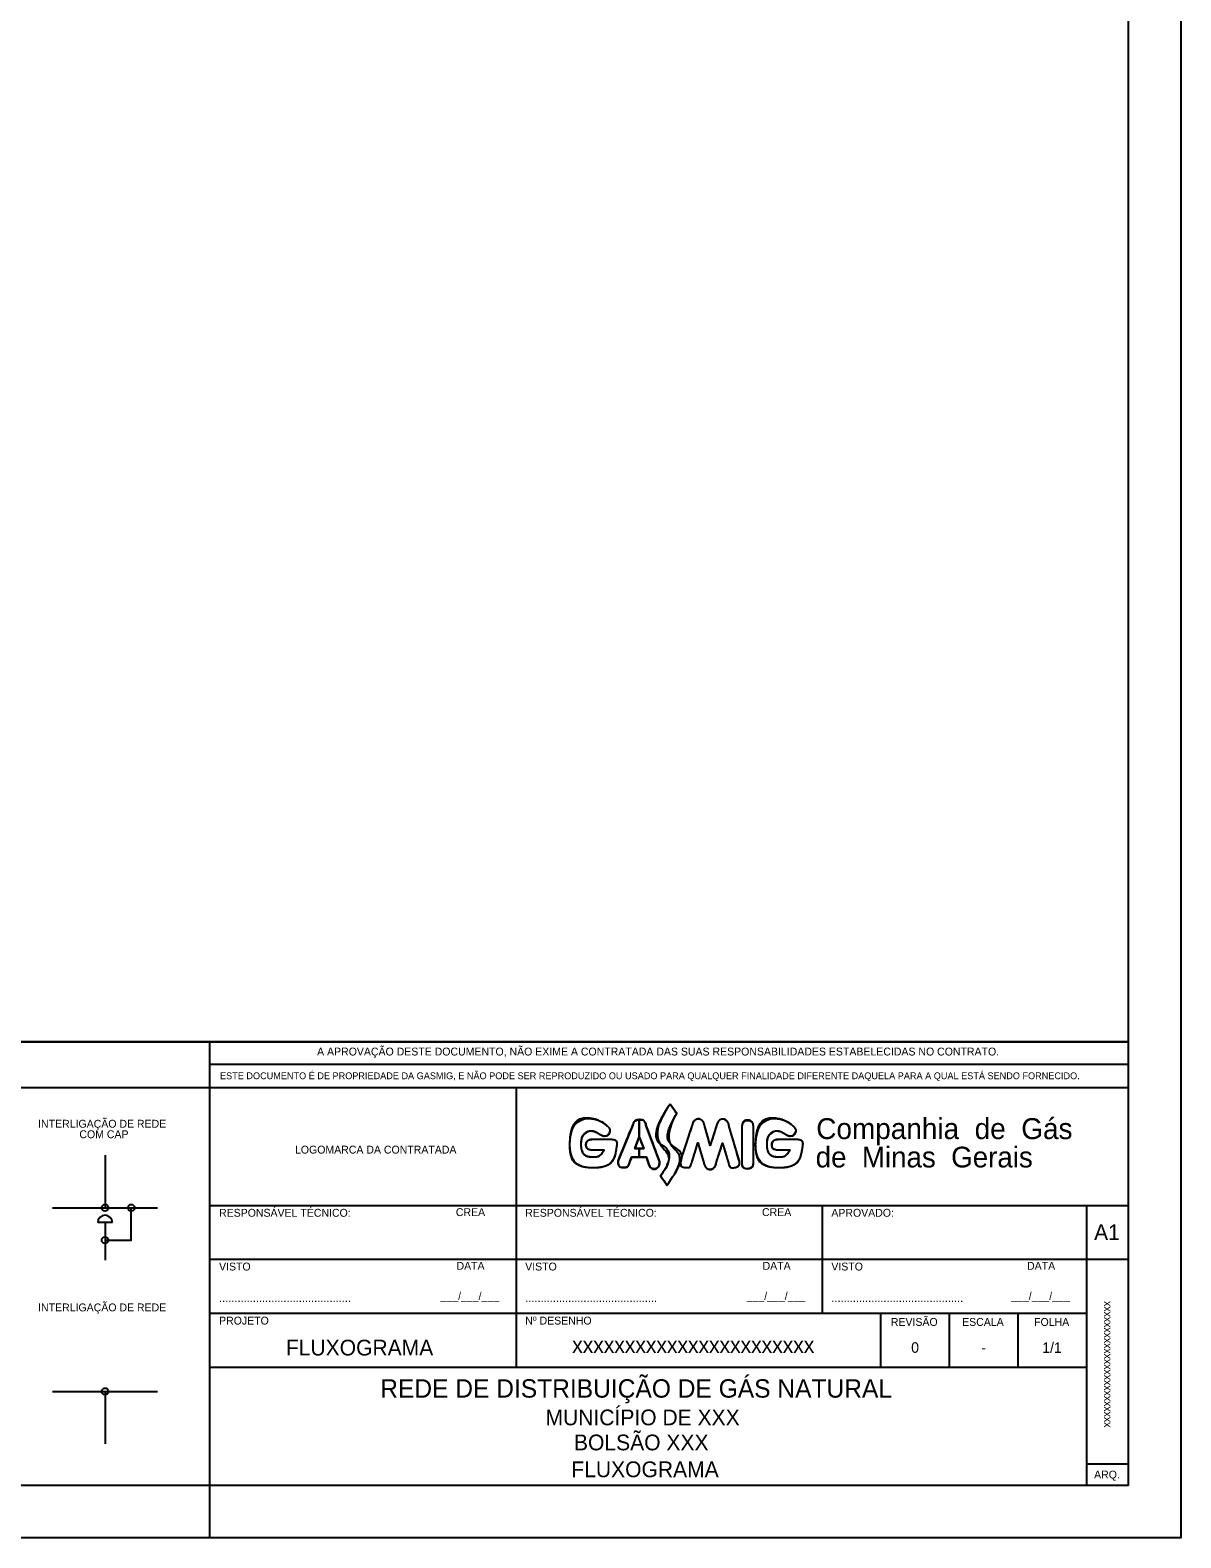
# Model space of a CAD drawing. Extents: x 0 to 841, y 0 to 594.
# Drawn here: x 621.7 to 841, y 0 to 287.3 of the extents above; entities that cross this region are included whole.
import ezdxf

# ---------------------------------------------------------------- set-up
doc = ezdxf.new("R2010")
doc.units = 0
for name, color, linetype in [('FORMATO', 7, 'Continuous'), ('LEGENDA', 7, 'Continuous'), ('LOGO_GASMIG', 7, 'Continuous'), ('MEIO_FIO_GUIA', 7, 'Continuous')]:
    doc.layers.add(name, color=color, linetype=linetype)

# ---------------------------------------------------------------- blocks, each defined once
blk = doc.blocks.new('Logotipo Gasmig')
for p, q in [((-27.74, 6.28), (-28.99, 8.08)), ((-41.08, 4), (-41.08, 4)), ((-36.11, 4.05), (-38.9, -2.73)), ((-34.87, 1.81), (-34.87, 5.1)), ((-34.87, 5.1), (-34.87, 1.81)), ((-31.02, -2.87), (-33.59, 4.03)), ((-24.88, 3.83), (-24.88, 3.83)), ((-21.35, 0.19), (-22.37, 3.79)), ((-20.2, 3.77), (-21.35, 0.19)), ((-15.8, -2.8), (-17.72, 3.75)), ((-13.19, 3.73), (-13.19, -3.01)), ((-5.67, 4), (-5.67, 4)), ((-45.99, 0.33), (-45.99, 0.33)), ((-43.65, 1.36), (-40.25, 1.36)), ((-42.52, 2.35), (-42.52, 2.35)), ((-39.2, 0.06), (-39.2, 0.06)), ((-35.74, -0.41), (-34.87, 1.81)), ((-34.87, 1.81), (-34.86, 1.84)), ((-34.86, 1.84), (-34, -0.41)), ((-24.79, -2.86), (-23.69, 0.7)), ((-23.69, 0.7), (-22.6, -2.95)), ((-20.14, -2.96), (-18.99, 0.64)), ((-18.99, 0.64), (-17.92, -2.98)), ((-10.58, 0.33), (-10.58, 0.33)), ((-8.24, 1.36), (-4.84, 1.36)), ((-7.11, 2.35), (-7.11, 2.35)), ((-3.79, 0.06), (-3.79, 0.06)), ((-43.69, -1.98), (-43.69, -1.98)), ((-41.77, -0.72), (-43.65, -0.72)), ((-41.64, -0.88), (-41.64, -0.88)), ((-38.9, -2.73), (-38.9, -3)), ((-36.67, -2.87), (-36.32, -2.07)), ((-36.32, -2.07), (-34.87, -2.07)), ((-34.87, -0.41), (-35.74, -0.41)), ((-34.87, -2.07), (-34.87, -0.41)), ((-34, -0.41), (-34.87, -0.41)), ((-34.87, -0.41), (-34.87, -2.07)), ((-34.87, -2.07), (-33.49, -2.07)), ((-33.49, -2.07), (-33.18, -2.99)), ((-8.28, -1.98), (-8.28, -1.98)), ((-6.36, -0.72), (-8.24, -0.72)), ((-6.23, -0.88), (-6.23, -0.88)), ((-43.71, -4.09), (-43.71, -4.09)), ((-37.97, -4), (-37.97, -4)), ((-31.02, -3.14), (-31.02, -2.88)), ((-30.82, -5.59), (-29.58, -7.39)), ((-26.09, -4.02), (-26.09, -4.02)), ((-16.53, -3.99), (-16.53, -3.99)), ((-15.28, -3.01), (-15.28, -3.01)), ((-8.3, -4.09), (-8.3, -4.09))]:
    blk.add_line(p, q)
for points, degree in [([(-28.99, 8.08), (-28.99, 8.08), (-27.74, 6.28), (-27.74, 6.28), (-27.74, 6.28), (-30.92, 0.42), (-25.06, -0.77), (-29.58, -7.39), (-29.58, -7.39), (-29.58, -7.39), (-30.82, -5.59), (-30.82, -5.59), (-30.82, -5.59), (-27.64, -1.21), (-33.47, 1.74), (-28.99, 8.08)], 3), ([(-28.99, 8.08), (-33.47, 1.74), (-27.64, -1.21), (-30.82, -5.59)], 2), ([(-29.58, -7.39), (-29.58, -7.39), (-29.58, -7.39), (-29.58, -7.39), (-25.06, -0.77), (-30.92, 0.42), (-27.74, 6.28)], 3), ([(-48.1, 0.37), (-48.03, 5.12), (-43.11, 5.7), (-41.08, 4)], 2), ([(-48.1, 0.37), (-48.1, -2.25), (-46.07, -4.09), (-43.71, -4.09), (-43.71, -4.09), (-41.56, -4.09), (-39.51, -2.68), (-39.2, 0.06), (-39.2, 0.06), (-39.05, 0.75), (-39.51, 1.36), (-40.25, 1.36), (-40.25, 1.36), (-40.25, 1.36), (-43.65, 1.36), (-43.65, 1.36), (-43.65, 1.36), (-45.02, 1.36), (-45.04, -0.72), (-43.65, -0.72), (-43.65, -0.72), (-43.65, -0.72), (-41.77, -0.72), (-41.77, -0.72), (-41.77, -0.72), (-41.5, -0.7), (-41.64, -0.8), (-41.64, -0.88), (-41.64, -0.88), (-42.33, -1.81), (-43.02, -1.99), (-43.69, -1.98), (-43.69, -1.98), (-45.11, -1.98), (-45.99, -0.76), (-45.99, 0.33), (-45.99, 0.33), (-45.99, 2.08), (-44, 3.26), (-42.52, 2.35), (-42.52, 2.35), (-41.18, 1.51), (-40.12, 3.19), (-41.08, 4), (-41.08, 4), (-43.11, 5.7), (-48.03, 5.12), (-48.1, 0.37)], 3), ([(-42.52, 2.35), (-44, 3.26), (-45.99, 2.08), (-45.99, 0.33)], 2), ([(-41.08, 4), (-40.12, 3.19), (-41.18, 1.51), (-42.52, 2.35)], 2), ([(-34.87, -2.07), (-34.87, -2.07), (-34.87, -2.07), (-34.87, -2.07), (-34.87, -2.07), (-34.87, -2.07), (-36.32, -2.07), (-36.32, -2.07), (-36.32, -2.07), (-36.32, -2.07), (-36.67, -2.87), (-36.67, -2.87), (-36.67, -2.87), (-36.89, -3.61), (-37.21, -4.05), (-37.97, -4), (-37.97, -4), (-38.46, -4), (-38.86, -3.64), (-38.9, -3), (-38.9, -3), (-38.9, -3), (-38.9, -2.8), (-38.9, -2.8), (-38.9, -2.8), (-38.9, -2.77), (-38.9, -2.75), (-38.9, -2.73), (-38.9, -2.73), (-38.9, -2.73), (-38.9, -2.75), (-38.9, -2.73), (-38.9, -2.73), (-36.11, 4.05), (-36.11, 4.05), (-36.11, 4.05), (-35.92, 4.73), (-35.39, 5.08), (-34.87, 5.1)], 3), ([(-34.87, 5.1), (-35.39, 5.08), (-35.92, 4.73), (-36.11, 4.05)], 2), ([(-34.87, 5.1), (-34.31, 5.12), (-33.75, 4.77), (-33.59, 4.03), (-33.59, 4.03), (-33.59, 4.03), (-31.02, -2.87), (-31.02, -2.87), (-31.02, -2.87), (-31.02, -2.87), (-31.02, -2.88), (-31.02, -2.88), (-31.02, -2.88), (-31.02, -2.88), (-31.02, -3.14), (-31.02, -3.14), (-31.02, -3.14), (-31.14, -4.23), (-32.76, -4.45), (-33.18, -2.99), (-33.18, -2.99), (-33.18, -2.99), (-33.49, -2.07), (-33.49, -2.07), (-33.49, -2.07), (-33.49, -2.07), (-34.87, -2.07), (-34.87, -2.07), (-34.87, -2.07), (-34.87, -2.07), (-34.87, -2.07), (-34.87, -2.07)], 3), ([(-33.59, 4.03), (-33.75, 4.77), (-34.31, 5.12), (-34.87, 5.1)], 2), ([(-26.99, -2.64), (-26.96, -2.54), (-24.88, 3.83), (-24.88, 3.83), (-24.88, 3.83), (-24.5, 5.24), (-22.68, 5.24), (-22.37, 3.79), (-22.37, 3.79), (-22.37, 3.79), (-21.35, 0.19), (-21.35, 0.19), (-21.35, 0.19), (-21.35, 0.19), (-20.2, 3.77), (-20.2, 3.77), (-20.2, 3.77), (-19.85, 5.24), (-18.03, 5.21), (-17.72, 3.75), (-17.72, 3.75), (-17.72, 3.75), (-15.8, -2.8), (-15.8, -2.8), (-15.8, -2.8), (-15.69, -3.23), (-15.95, -3.85), (-16.53, -3.99), (-16.53, -3.99), (-17.22, -4.15), (-17.76, -3.81), (-17.92, -2.98), (-17.92, -2.98), (-17.92, -2.98), (-18.99, 0.64), (-18.99, 0.64), (-18.99, 0.64), (-18.99, 0.64), (-20.14, -2.96), (-20.14, -2.96), (-20.14, -2.96), (-20.45, -4.4), (-22.29, -4.4), (-22.6, -2.95), (-22.6, -2.95), (-22.6, -2.95), (-23.69, 0.7), (-23.69, 0.7), (-23.69, 0.7), (-23.69, 0.7), (-24.79, -2.86), (-24.79, -2.86), (-24.79, -2.86), (-25.03, -3.62), (-25.29, -4.09), (-26.09, -4.02), (-26.09, -4.02), (-26.71, -3.95), (-27.1, -3.54), (-26.99, -2.64)], 3), ([(-24.88, 3.83), (-24.88, 3.83), (-26.96, -2.54), (-26.99, -2.64)], 2), ([(-22.37, 3.79), (-22.68, 5.24), (-24.5, 5.24), (-24.88, 3.83)], 2), ([(-17.72, 3.75), (-18.03, 5.21), (-19.85, 5.24), (-20.2, 3.77)], 2), ([(-15.24, 3.7), (-15.24, 1.38), (-15.28, -3.01), (-15.28, -3.01), (-15.28, -3.01), (-15.28, -4.38), (-13.19, -4.38), (-13.19, -3.01), (-13.19, -3.01), (-13.19, -3.01), (-13.19, 3.73), (-13.19, 3.73), (-13.19, 3.73), (-13.19, 5.09), (-15.28, 5.09), (-15.24, 3.7)], 3), ([(-15.28, -3.01), (-15.28, -3.01), (-15.24, 1.38), (-15.24, 3.7)], 2), ([(-15.24, 3.7), (-15.28, 5.09), (-13.19, 5.09), (-13.19, 3.73)], 2), ([(-12.69, 0.37), (-12.62, 5.12), (-7.7, 5.7), (-5.67, 4)], 2), ([(-12.69, 0.37), (-12.69, -2.25), (-10.66, -4.09), (-8.3, -4.09), (-8.3, -4.09), (-6.15, -4.09), (-4.1, -2.68), (-3.79, 0.06), (-3.79, 0.06), (-3.64, 0.75), (-4.1, 1.36), (-4.84, 1.36), (-4.84, 1.36), (-4.84, 1.36), (-8.24, 1.36), (-8.24, 1.36), (-8.24, 1.36), (-9.61, 1.36), (-9.63, -0.72), (-8.24, -0.72), (-8.24, -0.72), (-8.24, -0.72), (-6.36, -0.72), (-6.36, -0.72), (-6.36, -0.72), (-6.09, -0.7), (-6.23, -0.8), (-6.23, -0.88), (-6.23, -0.88), (-6.92, -1.81), (-7.61, -1.99), (-8.28, -1.98), (-8.28, -1.98), (-9.7, -1.98), (-10.58, -0.76), (-10.58, 0.33), (-10.58, 0.33), (-10.58, 2.08), (-8.6, 3.26), (-7.11, 2.35), (-7.11, 2.35), (-5.77, 1.51), (-4.71, 3.19), (-5.67, 4), (-5.67, 4), (-7.7, 5.7), (-12.62, 5.12), (-12.69, 0.37)], 3), ([(-7.11, 2.35), (-8.6, 3.26), (-10.58, 2.08), (-10.58, 0.33)], 2), ([(-5.67, 4), (-4.71, 3.19), (-5.77, 1.51), (-7.11, 2.35)], 2), ([(-43.71, -4.09), (-46.07, -4.09), (-48.1, -2.25), (-48.1, 0.37)], 2), ([(-45.99, 0.33), (-45.99, -0.76), (-45.11, -1.98), (-43.69, -1.98)], 2), ([(-43.65, -0.72), (-45.04, -0.72), (-45.02, 1.36), (-43.65, 1.36)], 2), ([(-39.2, 0.06), (-39.51, -2.68), (-41.56, -4.09), (-43.71, -4.09)], 2), ([(-40.25, 1.36), (-39.51, 1.36), (-39.05, 0.75), (-39.2, 0.06)], 2), ([(-34.87, 1.81), (-34.87, 1.81), (-35.74, -0.41), (-35.74, -0.41), (-35.74, -0.41), (-35.74, -0.41), (-34.87, -0.41), (-34.87, -0.41), (-34.87, -0.41), (-34.87, -0.41), (-34.87, -0.41), (-34.87, -0.41)], 3), ([(-34.87, -0.41), (-34.87, -0.41), (-34.87, -0.41), (-34.87, -0.41), (-34.87, -0.41), (-34.87, -0.41), (-34, -0.41), (-34, -0.41), (-34, -0.41), (-34, -0.41), (-34.86, 1.84), (-34.86, 1.84), (-34.86, 1.84), (-34.86, 1.84), (-34.87, 1.81), (-34.87, 1.81)], 3), ([(-8.3, -4.09), (-10.66, -4.09), (-12.69, -2.25), (-12.69, 0.37)], 2), ([(-10.58, 0.33), (-10.58, -0.76), (-9.7, -1.98), (-8.28, -1.98)], 2), ([(-8.24, -0.72), (-9.63, -0.72), (-9.61, 1.36), (-8.24, 1.36)], 2), ([(-3.79, 0.06), (-4.1, -2.68), (-6.15, -4.09), (-8.3, -4.09)], 2), ([(-4.84, 1.36), (-4.1, 1.36), (-3.64, 0.75), (-3.79, 0.06)], 2), ([(-43.69, -1.98), (-43.02, -1.99), (-42.33, -1.81), (-41.64, -0.88)], 2), ([(-41.64, -0.88), (-41.64, -0.8), (-41.5, -0.7), (-41.77, -0.72)], 2), ([(-37.97, -4), (-37.21, -4.05), (-36.89, -3.61), (-36.67, -2.87)], 2), ([(-31.02, -2.88), (-31.02, -2.88), (-31.02, -2.87), (-31.02, -2.87)], 2), ([(-26.99, -2.64), (-27.1, -3.54), (-26.71, -3.95), (-26.09, -4.02)], 2), ([(-26.09, -4.02), (-25.29, -4.09), (-25.03, -3.62), (-24.79, -2.86)], 2), ([(-16.53, -3.99), (-15.95, -3.85), (-15.69, -3.23), (-15.8, -2.8)], 2), ([(-8.28, -1.98), (-7.61, -1.99), (-6.92, -1.81), (-6.23, -0.88)], 2), ([(-6.23, -0.88), (-6.23, -0.8), (-6.09, -0.7), (-6.36, -0.72)], 2), ([(-38.9, -3), (-38.86, -3.64), (-38.46, -4), (-37.97, -4)], 2), ([(-33.18, -2.99), (-32.76, -4.45), (-31.14, -4.23), (-31.02, -3.14)], 2), ([(-22.6, -2.95), (-22.29, -4.4), (-20.45, -4.4), (-20.14, -2.96)], 2), ([(-17.92, -2.98), (-17.76, -3.81), (-17.22, -4.15), (-16.53, -3.99)], 2), ([(-13.19, -3.01), (-13.19, -3.01), (-13.19, -3.01), (-13.19, -3.01), (-13.19, -4.38), (-15.28, -4.38), (-15.28, -3.01)], 3)]:
    blk.add_open_spline(points, degree=degree)
for s, height, p in [('Companhia  de  Gás', 3.9809, (-1.14, 1.4)), ('de  Minas  Gerais', 3.9471, (-1.25, -4))]:
    blk.add_text(s, height=height).set_placement(p)

msp = doc.modelspace()

# ---------------------------------------------------------------- linework, layer by layer
at = {"layer": 'FORMATO'}
for p, q in [((831.01, 94.54), (25, 94.54)), ((656, 10), (656, 94.54)), ((656, 90.29), (831.01, 90.29)), ((25, 85.81), (656, 85.81)), ((656, 85.81), (831.01, 85.81)), ((714.34, 85.81), (714.34, 32.52)), ((656, 63.36), (831.01, 63.36)), ((772.67, 63.36), (772.67, 42.82)), ((823.07, 10), (823.07, 63.36)), ((656, 53.12), (831.01, 53.12)), ((655.99, 42.82), (823.07, 42.82)), ((783.86, 32.52), (783.86, 42.82)), ((796.93, 32.52), (796.93, 42.82)), ((810, 32.52), (810, 42.82)), ((655.99, 32.52), (823.07, 32.52)), ((823.07, 14.12), (831.01, 14.12)), ((831.01, 10), (5, 10)), ((656, 0), (656, 10))]:
    msp.add_line(p, q, dxfattribs=at)
msp.add_lwpolyline([(0, 594), (841, 594), (841, 0), (0, 0)], close=True, dxfattribs=at)
msp.add_lwpolyline([(831.01, 10), (831.01, 584), (25, 584), (25, 10)], dxfattribs=at)
at = {"layer": 'LEGENDA'}
for p, q in [((636, 72.91), (636, 62.91)), ((626, 62.91), (646, 62.91)), ((637.4, 60.07), (634.6, 60.07)), ((636, 60.07), (636, 52.91)), ((626, 27.91), (646, 27.91)), ((636, 27.91), (636, 17.91))]:
    msp.add_line(p, q, dxfattribs=at)
msp.add_lwpolyline([(636, 56.73), (641, 56.73), (641, 62.91)], dxfattribs=at)
for centre in [(636, 62.91), (641, 62.91), (636, 56.73), (636, 27.91)]:
    msp.add_circle(centre, 0.633, dxfattribs=at)
msp.add_arc((636, 60.07), 1.4, 0, 180, dxfattribs=at)
at = {"layer": 'MEIO_FIO_GUIA'}
msp.add_lwpolyline([(25, 584), (25, 94.54), (572.92, 94.54), (831.01, 94.54), (831.01, 251.27), (831.01, 584)], close=True, dxfattribs=at)

# ---------------------------------------------------------------- block references
at = {"layer": 'LOGO_GASMIG'}
msp.add_blockref('Logotipo Gasmig', (772.67, 74.59), dxfattribs=at)

# ---------------------------------------------------------------- texts
at = {"layer": 'FORMATO'}
for s, height, p in [('A APROVAÇÃO DESTE DOCUMENTO, NÃO EXIME A CONTRATADA DAS SUAS RESPONSABILIDADES ESTABELECIDAS NO CONTRATO.', 1.5, (676.41, 91.92)), ('ESTE DOCUMENTO É DE PROPRIEDADE DA GASMIG, E NÃO PODE SER REPRODUZIDO OU USADO PARA QUALQUER FINALIDADE DIFERENTE DAQUELA PARA A QUAL ESTÁ SENDO FORNECIDO.', 1.3, (657.91, 87.4)), ('LOGOMARCA DA CONTRATADA', 1.5, (672.2, 73.23)), ('RESPONSÁVEL TÉCNICO:', 1.5, (657.73, 61.19)), ('CREA', 1.5, (702.85, 61.32)), ('RESPONSÁVEL TÉCNICO:', 1.5, (716.06, 61.19)), ('CREA', 1.5, (761.19, 61.32)), ('APROVADO:', 1.5, (774.4, 61.19)), ('A1', 3, (824.47, 56.74)), ('VISTO', 1.5, (657.73, 50.95)), ('DATA', 1.5, (702.97, 51.08)), ('VISTO', 1.5, (716.06, 50.95)), ('DATA', 1.5, (761.3, 51.08)), ('VISTO', 1.5, (774.4, 50.95)), ('DATA', 1.5, (811.7, 51.08)), ('___/___/___', 1.5, (699.94, 45.36)), ('___/___/___', 1.5, (758.27, 45.36)), ('___/___/___', 1.5, (808.67, 45.36)), ('...........................................', 1.573, (657.73, 44.93)), ('...........................................', 1.573, (716.06, 44.93)), ('...........................................', 1.573, (774.4, 44.93)), ('PROJETO', 1.5, (657.73, 40.65)), ('Nº DESENHO', 1.5, (716.06, 40.65)), ('REVISÃO', 1.5, (785.74, 40.39)), ('ESCALA', 1.5, (799.33, 40.39)), ('FOLHA', 1.5, (813.04, 40.39)), ('xxxxxxxxxxxxxxxxxxxxxxx', 3, (725.02, 35.25)), ('1/1', 2, (814.59, 35.25)), ('0', 2, (789.62, 35.27)), ('-', 2, (803, 35.25)), ('MUNICÍPIO DE XXX', 3, (719.93, 21.45)), ('BOLSÃO XXX', 3, (725.36, 16.68)), ('FLUXOGRAMA', 3, (724.85, 11.56))]:
    msp.add_text(s, height=height, dxfattribs=at).set_placement(p)
for s, height, rotation, p in [('xxxxxxxxxxxxxxxxxxxxxxxx', 1.5, 90, (827.54, 21.05)), ('FLUXOGRAMA', 3, 360, (670.46, 34.75)), ('REDE DE DISTRIBUIÇÃO DE GÁS NATURAL', 3.5, 360, (688.44, 26.72)), ('ARQ.', 1.5, 360, (824.47, 11.31))]:
    msp.add_text(s, height=height, rotation=rotation, dxfattribs=at).set_placement(p)
at = {"layer": 'LEGENDA'}
for s, p in [('INTERLIGAÇÃO DE REDE', (623.25, 78.16)), ('COM CAP', (631.11, 76.16)), ('INTERLIGAÇÃO DE REDE', (623.25, 43.16))]:
    msp.add_text(s, height=1.5, dxfattribs=at).set_placement(p)

doc.saveas('drawing.dxf')
